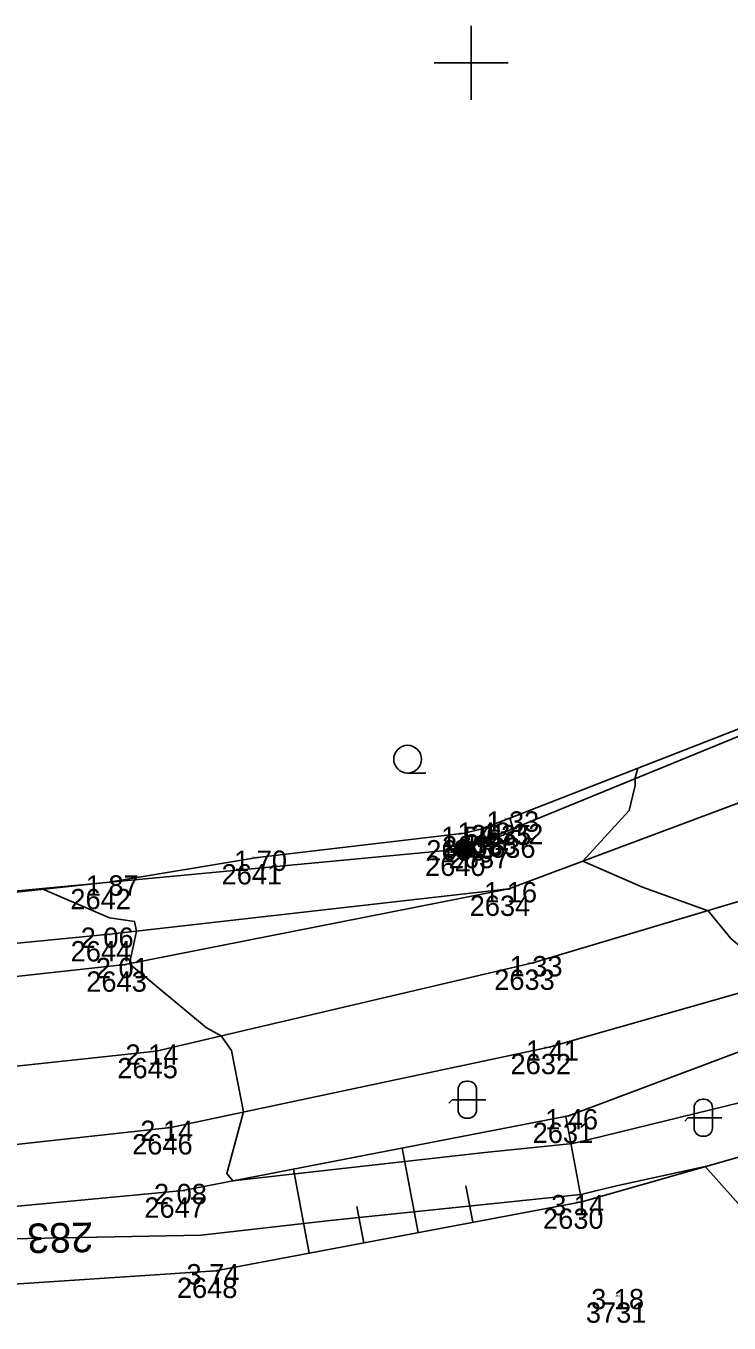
# Model space of a CAD drawing. Extents: x -740053 to -737517, y -1033516 to -1032488.
# Drawn here: x -738712.04 to -738693.03, y -1032634.07 to -1032599 of the extents above; entities that cross this region are included whole.
import ezdxf

# ---------------------------------------------------------------- set-up
doc = ezdxf.new("R2010")
doc.units = 0
for name, color, linetype in [('bod-cislo', 7, 'Continuous'), ('bod-oznac', 7, 'Continuous'), ('bod-vyska', 7, 'Continuous'), ('bod-vyska100', 7, 'Continuous'), ('Contours', 7, 'Continuous'), ('Contours text', 7, 'Continuous'), ('ctv-sit', 7, 'Continuous'), ('el-zariz', 7, 'Continuous'), ('osa-komunikace', 7, 'Continuous'), ('ploty', 7, 'Continuous'), ('Ploty-Vjezd', 7, 'Continuous'), ('podezdivka', 7, 'Continuous'), ('Rozhrani-ploch', 7, 'Continuous'), ('Sdelovaci', 7, 'Continuous'), ('silnice', 7, 'Continuous'), ('Technické šrafy', 7, 'Continuous'), ('Terenni-hrana', 7, 'Continuous'), ('Znacky-kultury', 7, 'Continuous')]:
    doc.layers.add(name, color=color, linetype=linetype)

# ---------------------------------------------------------------- blocks, each defined once
blk = doc.blocks.new('_U')
for points in [[(-4999.05, -6988.837), (-4999.045, -6988.908), (-4999.045, -6988.765), (-4999.045, -6988.765)], [(-4999.045, -6988.765), (-4999.03, -6988.977), (-4999.03, -6988.696), (-4999.03, -6988.696)], [(-4999.03, -6988.977), (-4999.045, -6988.765), (-4999.045, -6988.908), (-4999.045, -6988.908)], [(-4999.03, -6988.696), (-4999.005, -6989.044), (-4999.005, -6988.629), (-4999.005, -6988.629)], [(-4999.005, -6989.044), (-4999.03, -6988.696), (-4999.03, -6988.977), (-4999.03, -6988.977)], [(-4999.005, -6988.629), (-4998.971, -6989.107), (-4998.971, -6988.566), (-4998.971, -6988.566)], [(-4998.971, -6989.107), (-4999.005, -6988.629), (-4999.005, -6989.044), (-4999.005, -6989.044)], [(-4998.971, -6988.566), (-4998.928, -6989.164), (-4998.928, -6988.509), (-4998.928, -6988.509)], [(-4998.928, -6989.164), (-4998.971, -6988.566), (-4998.971, -6989.107), (-4998.971, -6989.107)], [(-4998.928, -6988.509), (-4998.878, -6989.214), (-4998.878, -6988.459), (-4998.878, -6988.459)], [(-4998.878, -6989.214), (-4998.928, -6988.509), (-4998.928, -6989.164), (-4998.928, -6989.164)], [(-4998.878, -6988.459), (-4998.82, -6989.257), (-4998.82, -6988.416), (-4998.82, -6988.416)], [(-4998.82, -6989.257), (-4998.878, -6988.459), (-4998.878, -6989.214), (-4998.878, -6989.214)], [(-4998.82, -6988.416), (-4998.758, -6989.291), (-4998.758, -6988.382), (-4998.758, -6988.382)], [(-4998.758, -6989.291), (-4998.82, -6988.416), (-4998.82, -6989.257), (-4998.82, -6989.257)], [(-4998.758, -6988.382), (-4998.691, -6989.316), (-4998.691, -6988.357), (-4998.691, -6988.357)], [(-4998.691, -6989.316), (-4998.758, -6988.382), (-4998.758, -6989.291), (-4998.758, -6989.291)], [(-4998.691, -6988.357), (-4998.621, -6989.331), (-4998.621, -6988.342), (-4998.621, -6988.342)], [(-4998.621, -6989.331), (-4998.691, -6988.357), (-4998.691, -6989.316), (-4998.691, -6989.316)], [(-4998.621, -6988.342), (-4998.55, -6989.336), (-4998.55, -6988.337), (-4998.55, -6988.337)], [(-4998.55, -6989.336), (-4998.621, -6988.342), (-4998.621, -6989.331), (-4998.621, -6989.331)], [(-4998.55, -6988.337), (-4998.479, -6989.331), (-4998.479, -6988.342), (-4998.479, -6988.342)], [(-4998.479, -6989.331), (-4998.55, -6988.337), (-4998.55, -6989.336), (-4998.55, -6989.336)], [(-4998.479, -6988.342), (-4998.409, -6989.316), (-4998.409, -6988.357), (-4998.409, -6988.357)], [(-4998.409, -6989.316), (-4998.479, -6988.342), (-4998.479, -6989.331), (-4998.479, -6989.331)], [(-4998.409, -6988.357), (-4998.343, -6989.291), (-4998.343, -6988.382), (-4998.343, -6988.382)], [(-4998.343, -6989.291), (-4998.409, -6988.357), (-4998.409, -6989.316), (-4998.409, -6989.316)], [(-4998.343, -6988.382), (-4998.28, -6989.257), (-4998.28, -6988.416), (-4998.28, -6988.416)], [(-4998.28, -6989.257), (-4998.343, -6988.382), (-4998.343, -6989.291), (-4998.343, -6989.291)], [(-4998.28, -6988.416), (-4998.223, -6989.214), (-4998.223, -6988.459), (-4998.223, -6988.459)], [(-4998.223, -6989.214), (-4998.28, -6988.416), (-4998.28, -6989.257), (-4998.28, -6989.257)], [(-4998.223, -6988.459), (-4998.173, -6989.164), (-4998.173, -6988.509), (-4998.173, -6988.509)], [(-4998.173, -6989.164), (-4998.223, -6988.459), (-4998.223, -6989.214), (-4998.223, -6989.214)], [(-4998.173, -6988.509), (-4998.13, -6989.107), (-4998.13, -6988.566), (-4998.13, -6988.566)], [(-4998.13, -6989.107), (-4998.173, -6988.509), (-4998.173, -6989.164), (-4998.173, -6989.164)], [(-4998.13, -6988.566), (-4998.096, -6989.044), (-4998.096, -6988.629), (-4998.096, -6988.629)], [(-4998.096, -6989.044), (-4998.13, -6988.566), (-4998.13, -6989.107), (-4998.13, -6989.107)], [(-4998.096, -6988.629), (-4998.071, -6988.977), (-4998.071, -6988.696), (-4998.071, -6988.696)], [(-4998.071, -6988.977), (-4998.096, -6988.629), (-4998.096, -6989.044), (-4998.096, -6989.044)], [(-4998.071, -6988.696), (-4998.056, -6988.908), (-4998.056, -6988.765), (-4998.056, -6988.765)], [(-4998.056, -6988.908), (-4998.071, -6988.696), (-4998.071, -6988.977), (-4998.071, -6988.977)], [(-4998.05, -6988.837), (-4998.056, -6988.765), (-4998.056, -6988.908), (-4998.056, -6988.908)]]:
    blk.add_lwpolyline(points, close=True)
blk = doc.blocks.new('el_sloup')
blk.add_circle((0, 0), 0.5)
blk.add_blockref('_U', (4998.55, 6988.837))
blk = doc.blocks.new('p_neplod')
for p, q in [((0.052, 1.005), (-0.044, 1.005)), ((-0.824, 0.004), (-0.994, -0.184)), ((1.002, 0.004), (-0.824, 0.004)), ((-0.494, 0.555), (-0.494, -0.548)), ((0.502, -0.548), (0.502, 0.555)), ((-0.044, -0.998), (0.052, -0.998))]:
    blk.add_line(p, q)
for centre, start, end in [((-0.044, 0.555), 90, 180), ((0.052, 0.555), 0, 90), ((-0.044, -0.548), 180, 270), ((0.052, -0.548), 270, 0)]:
    blk.add_arc(centre, 0.45, start, end)
blk = doc.blocks.new('p_zahr')
blk.add_line((0, -0.75), (0.993, -0.75))
blk.add_circle((0, 0), 0.75)
blk = doc.blocks.new('POINT_DISPLAY')
blk.add_line((0, 0), (0, 0))
blk = doc.blocks.new('ctvsit')
for p, q in [((0, -2), (0, 2)), ((2, 0), (-2, 0))]:
    blk.add_line(p, q)

msp = doc.modelspace()

# ---------------------------------------------------------------- linework, layer by layer
at = {"layer": 'Contours'}
for points in [[(-738674.176, -1032619.78), (-738674.7, -1032620.069), (-738675.668, -1032620.535), (-738676.355, -1032620.795), (-738679.161, -1032621.954), (-738680.748, -1032622.592), (-738681.722, -1032623.069), (-738684.463, -1032624.235), (-738684.663, -1032624.409), (-738685.398, -1032624.69), (-738685.786, -1032624.784), (-738686.336, -1032624.844), (-738690.782, -1032625.989), (-738691.248, -1032625.307), (-738691.624, -1032624.827), (-738692.982, -1032623.673), (-738693.598, -1032622.921), (-738695.368, -1032622.283), (-738696.983, -1032621.582), (-738695.728, -1032620.214), (-738695.568, -1032619.535), (-738695.572, -1032619.332), (-738695.495, -1032619.066)], [(-738673.049, -1032626.1), (-738675.104, -1032623.02), (-738675.691, -1032622.326), (-738676.313, -1032622.616), (-738677.126, -1032623.104), (-738677.611, -1032623.305), (-738678.724, -1032623.751), (-738684.781, -1032625.942), (-738686.6, -1032626.638), (-738688.517, -1032627.105), (-738689.404, -1032627.297), (-738697.254, -1032629.216), (-738699.629, -1032629.462), (-738706.445, -1032630.229), (-738706.608, -1032630.027), (-738706.158, -1032628.364), (-738706.481, -1032626.699), (-738706.759, -1032626.307), (-738707.157, -1032626.093), (-738709.238, -1032624.356), (-738709.051, -1032623.478), (-738709.105, -1032623.213), (-738709.776, -1032623.115), (-738711.586, -1032622.343)], [(-738691.646, -1032632.111), (-738692.477, -1032631.182), (-738693.678, -1032629.842), (-738696.076, -1032630.361), (-738697.04, -1032630.597), (-738703.814, -1032631.3), (-738707.302, -1032631.693), (-738712.466, -1032631.794), (-738712.64, -1032631.79)]]:
    msp.add_lwpolyline(points, dxfattribs=at)
at = {"layer": 'osa-komunikace'}
for p, q in [((-738689.87, -1032621.81), (-738698.33, -1032624.33)), ((-738698.33, -1032624.33), (-738708.52, -1032626.72)), ((-738708.52, -1032626.72), (-738712.64, -1032627.164))]:
    msp.add_line(p, q, dxfattribs=at)
at = {"layer": 'ploty'}
msp.add_line((-738709.79, -1032622.15), (-738712.64, -1032622.456), dxfattribs=at)
at = {"layer": 'Ploty-Vjezd'}
msp.add_line((-738705.78, -1032621.48), (-738709.79, -1032622.15), dxfattribs=at)
at = {"layer": 'podezdivka'}
for p, q in [((-738691.82, -1032617.63), (-738698.96, -1032620.42)), ((-738698.96, -1032620.42), (-738699.74, -1032620.72)), ((-738700.18, -1032620.83), (-738705.78, -1032621.48)), ((-738699.74, -1032620.72), (-738700.18, -1032620.83))]:
    msp.add_line(p, q, dxfattribs=at)
at = {"layer": 'Rozhrani-ploch'}
for p, q in [((-738698.96, -1032620.42), (-738698.85, -1032620.76)), ((-738699.56, -1032621.04), (-738699.74, -1032620.72)), ((-738698.85, -1032620.76), (-738699.56, -1032621.04))]:
    msp.add_line(p, q, dxfattribs=at)
at = {"layer": 'Sdelovaci'}
for p, q in [((-738681.94, -1032613.77), (-738700.2, -1032621.25)), ((-738700.2, -1032621.25), (-738712.64, -1032622.417))]:
    msp.add_line(p, q, dxfattribs=at)
at = {"layer": 'silnice'}
for p, q in [((-738691.24, -1032619.43), (-738698.98, -1032622.33)), ((-738698.98, -1032622.33), (-738709.36, -1032624.38)), ((-738688.72, -1032624), (-738697.89, -1032626.61)), ((-738709.36, -1032624.38), (-738712.64, -1032624.74)), ((-738697.89, -1032626.61), (-738708.12, -1032628.78)), ((-738708.12, -1032628.78), (-738712.64, -1032629.283))]:
    msp.add_line(p, q, dxfattribs=at)
at = {"layer": 'Technické šrafy'}
for p, q in [((-738697.01, -1032630.79), (-738697.445, -1032628.485)), ((-738701.432, -1032631.625), (-738701.863, -1032629.341)), ((-738704.38, -1032632.182), (-738704.808, -1032629.912)), ((-738699.958, -1032631.347), (-738700.143, -1032630.364)), ((-738702.906, -1032631.904), (-738703.091, -1032630.921))]:
    msp.add_line(p, q, dxfattribs=at)
at = {"layer": 'Terenni-hrana'}
for p, q in [((-738709.77, -1032623.56), (-738698.98, -1032622.33)), ((-738709.77, -1032623.56), (-738712.64, -1032623.84)), ((-738685.34, -1032623.94), (-738697.37, -1032628.47)), ((-738687.49, -1032628.08), (-738697.01, -1032630.79)), ((-738697.37, -1032628.47), (-738707.79, -1032630.49)), ((-738707.79, -1032630.49), (-738712.64, -1032630.943)), ((-738697.01, -1032630.79), (-738706.91, -1032632.66)), ((-738706.91, -1032632.66), (-738712.64, -1032633.039))]:
    msp.add_line(p, q, dxfattribs=at)

# ---------------------------------------------------------------- block references
at = {"layer": 'bod-oznac'}
for p in [(-738698.96, -1032620.42), (-738700.18, -1032620.83), (-738699.74, -1032620.72), (-738698.85, -1032620.76), (-738700.2, -1032621.25), (-738699.56, -1032621.04), (-738705.78, -1032621.48), (-738709.79, -1032622.15), (-738698.98, -1032622.33), (-738709.77, -1032623.56), (-738709.36, -1032624.38), (-738698.33, -1032624.33), (-738708.52, -1032626.72), (-738697.89, -1032626.61), (-738697.37, -1032628.47), (-738708.12, -1032628.78), (-738707.79, -1032630.49), (-738697.01, -1032630.79), (-738706.91, -1032632.66), (-738695.93, -1032633.33)]:
    msp.add_blockref('POINT_DISPLAY', p, dxfattribs=at)
at = {"layer": 'ctv-sit', "xscale": 0.5, "yscale": 0.5, "rotation": 180}
msp.add_blockref('ctvsit', (-738700, -1032600), dxfattribs=at)
at = {"layer": 'el-zariz', "xscale": 0.5, "yscale": 0.5}
msp.add_blockref('el_sloup', (-738700.2, -1032621.25), dxfattribs=at)
at = {"layer": 'Znacky-kultury', "xscale": 0.5, "yscale": 0.5}
for name, p in [('p_zahr', (-738701.721, -1032618.825)), ('p_neplod', (-738700.107, -1032628.034)), ('p_neplod', (-738693.729, -1032628.523))]:
    msp.add_blockref(name, p, dxfattribs=at)

# ---------------------------------------------------------------- texts
at = {"layer": 'bod-cislo'}
for s, p in [('2635', (-738700.008, -1032621.153)), ('2638', (-738700.788, -1032621.453)), ('2636', (-738699.898, -1032621.493)), ('2639', (-738701.215, -1032621.563)), ('2637', (-738700.608, -1032621.773)), ('2641', (-738706.749, -1032622.213)), ('2640', (-738701.248, -1032621.983)), ('2642', (-738710.838, -1032622.883)), ('2634', (-738700.041, -1032623.063)), ('2644', (-738710.831, -1032624.293)), ('2643', (-738710.408, -1032625.113)), ('2633', (-738699.378, -1032625.063)), ('2645', (-738709.568, -1032627.453)), ('2632', (-738698.938, -1032627.343)), ('2631', (-738698.339, -1032629.203)), ('2646', (-738709.168, -1032629.513)), ('2647', (-738708.838, -1032631.223)), ('2630', (-738698.058, -1032631.523)), ('2648', (-738707.958, -1032633.393)), ('3731', (-738696.899, -1032634.063))]:
    msp.add_text(s, height=0.55, dxfattribs=at).set_placement(p)
at = {"layer": 'bod-vyska'}
for s, p in [('1 33', (-738699.592, -1032620.787)), ('1 43', (-738700.372, -1032621.087)), ('1 32', (-738699.482, -1032621.127)), ('1 50', (-738700.812, -1032621.197)), ('1 36', (-738700.192, -1032621.407)), ('1 70', (-738706.412, -1032621.847)), ('1 40', (-738700.832, -1032621.617)), ('1 87', (-738710.422, -1032622.517)), ('1 16', (-738699.651, -1032622.697)), ('2 06', (-738710.559, -1032623.927)), ('2 01', (-738710.149, -1032624.747)), ('1 33', (-738698.962, -1032624.697)), ('2 14', (-738709.348, -1032627.087)), ('1 41', (-738698.522, -1032626.977)), ('1 46', (-738698.002, -1032628.837)), ('2 14', (-738708.948, -1032629.147)), ('2 08', (-738708.579, -1032630.857)), ('3 14', (-738697.838, -1032631.157)), ('3 74', (-738707.699, -1032633.027)), ('3 18', (-738696.758, -1032633.697))]:
    msp.add_text(s, height=0.55, dxfattribs=at).set_placement(p)
at = {"layer": 'bod-vyska100'}
for s, p in [('281 33', (-738699.12, -1032620.453)), ('281 50', (-738700.34, -1032620.863)), ('281 43', (-738699.9, -1032620.753)), ('281 32', (-738699.01, -1032620.793)), ('281 40', (-738700.36, -1032621.283)), ('281 36', (-738699.72, -1032621.073)), ('281 70', (-738705.94, -1032621.513)), ('281 87', (-738709.95, -1032622.183)), ('281 16', (-738699.143, -1032622.363)), ('282 06', (-738709.937, -1032623.593)), ('282 01', (-738709.527, -1032624.413)), ('281 33', (-738698.49, -1032624.363)), ('282 14', (-738708.691, -1032626.753)), ('281 41', (-738698.05, -1032626.643)), ('281 46', (-738697.53, -1032628.503)), ('282 14', (-738708.291, -1032628.813)), ('282 08', (-738707.957, -1032630.523)), ('283 14', (-738697.181, -1032630.823)), ('283 74', (-738707.077, -1032632.693)), ('283 18', (-738696.101, -1032633.363))]:
    msp.add_text(s, height=0.05, dxfattribs=at).set_placement(p)
at = {"layer": 'Contours text'}
msp.add_text('283', height=0.8, rotation=181.1253, dxfattribs=at).set_placement((-738710.228, -1032631.35))

doc.saveas('drawing.dxf')
